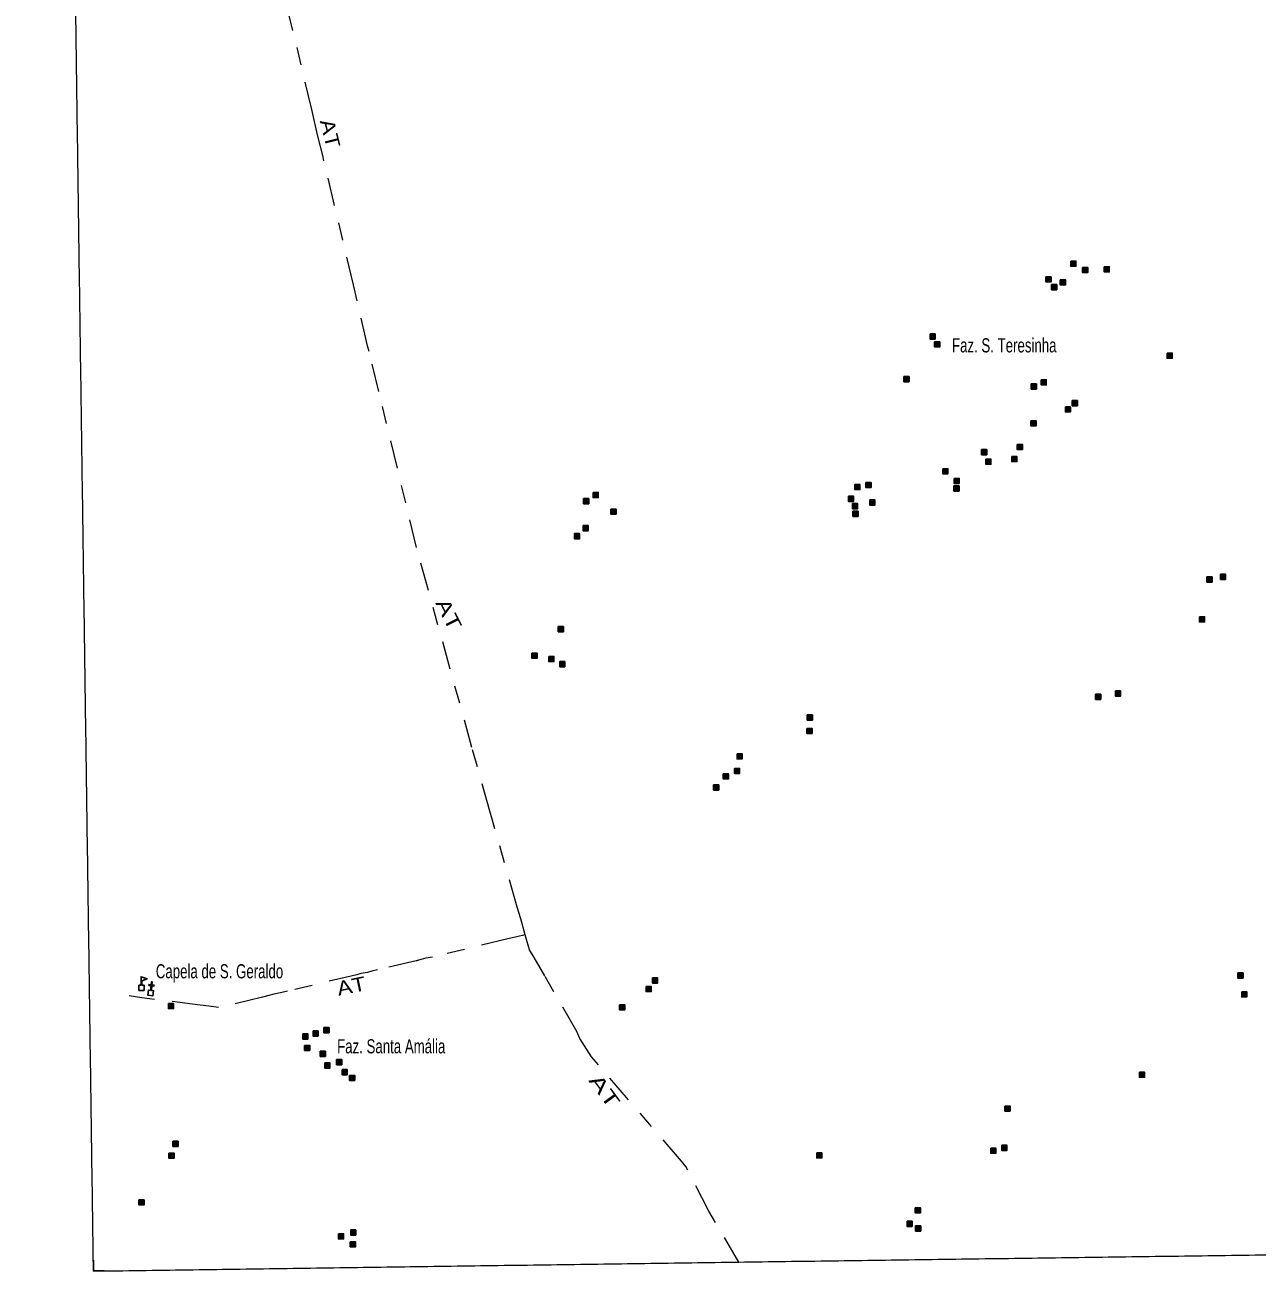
# Model space of a CAD drawing. Extents: x 265.7 to 292.1, y 7676.2 to 7704.2.
# Drawn here: x 265.72 to 272.68, y 7676.18 to 7683.22 of the extents above; entities that cross this region are included whole.
import ezdxf
from ezdxf.enums import TextEntityAlignment as Align

# ---------------------------------------------------------------- set-up
doc = ezdxf.new("R2010")
doc.units = 0
doc.header["$LTSCALE"] = 0.032
doc.linetypes.add('DOT_DASHED', pattern=[7.7, 5, -1.2, 0.3, -1.2])
for name, color, linetype, lineweight in [('2', 7, 'Continuous', 25), ('4', 7, 'Continuous', 25), ('56', 7, 'DOT_DASHED', 13), ('6', 7, 'Continuous', 25), ('63', 7, 'Continuous', 13)]:
    doc.layers.add(name, color=color, linetype=linetype, lineweight=lineweight)
doc.layers.add('61', color=7, linetype='Continuous')

msp = doc.modelspace()

# ---------------------------------------------------------------- hatches: boundary and pattern name
at = {"layer": '2'}
for points in [[(271.6304, 7681.8855), (271.6594, 7681.8855), (271.6594, 7681.8565), (271.6304, 7681.8565)], [(271.6974, 7681.8498), (271.7264, 7681.8498), (271.7264, 7681.8208), (271.6974, 7681.8208)], [(271.8193, 7681.8532), (271.8483, 7681.8532), (271.8483, 7681.8242), (271.8193, 7681.8242)], [(271.4902, 7681.7962), (271.5192, 7681.7962), (271.5192, 7681.7672), (271.4902, 7681.7672)], [(271.5223, 7681.7523), (271.5513, 7681.7523), (271.5513, 7681.7233), (271.5223, 7681.7233)], [(271.5707, 7681.7797), (271.5997, 7681.7797), (271.5997, 7681.7507), (271.5707, 7681.7507)], [(270.8346, 7681.4738), (270.8636, 7681.4738), (270.8636, 7681.4448), (270.8346, 7681.4448)], [(270.8605, 7681.4294), (270.8895, 7681.4294), (270.8895, 7681.4004), (270.8605, 7681.4004)], [(272.1751, 7681.3649), (272.2041, 7681.3649), (272.2041, 7681.3359), (272.1751, 7681.3359)], [(270.6869, 7681.2325), (270.7159, 7681.2325), (270.7159, 7681.2035), (270.6869, 7681.2035)], [(271.4069, 7681.1906), (271.4359, 7681.1906), (271.4359, 7681.1616), (271.4069, 7681.1616)], [(271.4631, 7681.2148), (271.4921, 7681.2148), (271.4921, 7681.1858), (271.4631, 7681.1858)], [(271.5997, 7681.0615), (271.6287, 7681.0615), (271.6287, 7681.0325), (271.5997, 7681.0325)], [(271.6385, 7681.097), (271.6675, 7681.097), (271.6675, 7681.068), (271.6385, 7681.068)], [(271.4052, 7680.9824), (271.4342, 7680.9824), (271.4342, 7680.9534), (271.4052, 7680.9534)], [(271.3277, 7680.8492), (271.3567, 7680.8492), (271.3567, 7680.8202), (271.3277, 7680.8202)], [(271.1259, 7680.8201), (271.1549, 7680.8201), (271.1549, 7680.7911), (271.1259, 7680.7911)], [(271.1502, 7680.766), (271.1792, 7680.766), (271.1792, 7680.737), (271.1502, 7680.737)], [(271.2971, 7680.7806), (271.3261, 7680.7806), (271.3261, 7680.7516), (271.2971, 7680.7516)], [(270.9065, 7680.712), (270.9355, 7680.712), (270.9355, 7680.683), (270.9065, 7680.683)], [(270.4093, 7680.6224), (270.4383, 7680.6224), (270.4383, 7680.5934), (270.4093, 7680.5934)], [(270.4722, 7680.6337), (270.5012, 7680.6337), (270.5012, 7680.6047), (270.4722, 7680.6047)], [(270.9695, 7680.6144), (270.9985, 7680.6144), (270.9985, 7680.5854), (270.9695, 7680.5854)], [(270.9711, 7680.6572), (271.0001, 7680.6572), (271.0001, 7680.6282), (270.9711, 7680.6282)], [(268.93, 7680.578), (268.959, 7680.578), (268.959, 7680.549), (268.93, 7680.549)], [(270.3731, 7680.5562), (270.4021, 7680.5562), (270.4021, 7680.5272), (270.3731, 7680.5272)], [(268.876, 7680.5426), (268.905, 7680.5426), (268.905, 7680.5136), (268.876, 7680.5136)], [(269.0309, 7680.4837), (269.0599, 7680.4837), (269.0599, 7680.4547), (269.0309, 7680.4547)], [(270.3964, 7680.5143), (270.4254, 7680.5143), (270.4254, 7680.4853), (270.3964, 7680.4853)], [(270.4941, 7680.5353), (270.5231, 7680.5353), (270.5231, 7680.5063), (270.4941, 7680.5063)], [(270.3989, 7680.4715), (270.4279, 7680.4715), (270.4279, 7680.4425), (270.3989, 7680.4425)], [(268.8244, 7680.3448), (268.8534, 7680.3448), (268.8534, 7680.3158), (268.8244, 7680.3158)], [(268.8734, 7680.39), (268.9024, 7680.39), (268.9024, 7680.361), (268.8734, 7680.361)], [(272.4003, 7680.1002), (272.4293, 7680.1002), (272.4293, 7680.0712), (272.4003, 7680.0712)], [(272.477, 7680.1148), (272.506, 7680.1148), (272.506, 7680.0858), (272.477, 7680.0858)], [(272.3575, 7679.8752), (272.3865, 7679.8752), (272.3865, 7679.8462), (272.3575, 7679.8462)], [(268.7331, 7679.8193), (268.7621, 7679.8193), (268.7621, 7679.7903), (268.7331, 7679.7903)], [(268.5839, 7679.6693), (268.6129, 7679.6693), (268.6129, 7679.6403), (268.5839, 7679.6403)], [(268.679, 7679.6507), (268.708, 7679.6507), (268.708, 7679.6217), (268.679, 7679.6217)], [(268.7411, 7679.6217), (268.7701, 7679.6217), (268.7701, 7679.5927), (268.7411, 7679.5927)], [(271.7709, 7679.4368), (271.7999, 7679.4368), (271.7999, 7679.4078), (271.7709, 7679.4078)], [(271.883, 7679.4554), (271.912, 7679.4554), (271.912, 7679.4264), (271.883, 7679.4264)], [(270.1407, 7679.3198), (270.1697, 7679.3198), (270.1697, 7679.2908), (270.1407, 7679.2908)], [(270.1386, 7679.2441), (270.1676, 7679.2441), (270.1676, 7679.2151), (270.1386, 7679.2151)], [(269.7435, 7679.1003), (269.7725, 7679.1003), (269.7725, 7679.0713), (269.7435, 7679.0713)], [(269.729, 7679.0181), (269.758, 7679.0181), (269.758, 7678.9891), (269.729, 7678.9891)], [(269.6111, 7678.9244), (269.6401, 7678.9244), (269.6401, 7678.8954), (269.6111, 7678.8954)], [(269.666, 7678.9873), (269.695, 7678.9873), (269.695, 7678.9583), (269.666, 7678.9583)], [(269.2658, 7677.8333), (269.2948, 7677.8333), (269.2948, 7677.8043), (269.2658, 7677.8043)], [(272.5755, 7677.8615), (272.6045, 7677.8615), (272.6045, 7677.8325), (272.5755, 7677.8325)], [(269.2295, 7677.7848), (269.2585, 7677.7848), (269.2585, 7677.7558), (269.2295, 7677.7558)], [(272.5965, 7677.7549), (272.6255, 7677.7549), (272.6255, 7677.7259), (272.5965, 7677.7259)], [(266.5291, 7677.6888), (266.5581, 7677.6888), (266.5581, 7677.6598), (266.5291, 7677.6598)], [(269.0801, 7677.6816), (269.1091, 7677.6816), (269.1091, 7677.6526), (269.0801, 7677.6526)], [(267.2885, 7677.517), (267.3175, 7677.517), (267.3175, 7677.488), (267.2885, 7677.488)], [(267.3465, 7677.5337), (267.3755, 7677.5337), (267.3755, 7677.5047), (267.3465, 7677.5047)], [(267.408, 7677.5523), (267.437, 7677.5523), (267.437, 7677.5233), (267.408, 7677.5233)], [(267.299, 7677.4523), (267.328, 7677.4523), (267.328, 7677.4233), (267.299, 7677.4233)], [(267.3878, 7677.4191), (267.4168, 7677.4191), (267.4168, 7677.3901), (267.3878, 7677.3901)], [(267.4127, 7677.353), (267.4417, 7677.353), (267.4417, 7677.324), (267.4127, 7677.324)], [(267.4797, 7677.3717), (267.5087, 7677.3717), (267.5087, 7677.3427), (267.4797, 7677.3427)], [(267.5113, 7677.3151), (267.5403, 7677.3151), (267.5403, 7677.2861), (267.5113, 7677.2861)], [(267.5532, 7677.2828), (267.5822, 7677.2828), (267.5822, 7677.2538), (267.5532, 7677.2538)], [(272.0186, 7677.3006), (272.0476, 7677.3006), (272.0476, 7677.2716), (272.0186, 7677.2716)], [(271.2584, 7677.1094), (271.2874, 7677.1094), (271.2874, 7677.0804), (271.2584, 7677.0804)], [(266.5549, 7676.9099), (266.5839, 7676.9099), (266.5839, 7676.8809), (266.5549, 7676.8809)], [(271.2402, 7676.8878), (271.2692, 7676.8878), (271.2692, 7676.8588), (271.2402, 7676.8588)], [(266.5322, 7676.843), (266.5612, 7676.843), (266.5612, 7676.814), (266.5322, 7676.814)], [(270.1947, 7676.8447), (270.2237, 7676.8447), (270.2237, 7676.8157), (270.1947, 7676.8157)], [(271.1778, 7676.8711), (271.2068, 7676.8711), (271.2068, 7676.8421), (271.1778, 7676.8421)], [(266.3628, 7676.5791), (266.3918, 7676.5791), (266.3918, 7676.5501), (266.3628, 7676.5501)], [(270.7516, 7676.5339), (270.7806, 7676.5339), (270.7806, 7676.5049), (270.7516, 7676.5049)], [(267.5596, 7676.4089), (267.5886, 7676.4089), (267.5886, 7676.3799), (267.5596, 7676.3799)], [(270.7047, 7676.4581), (270.7337, 7676.4581), (270.7337, 7676.4291), (270.7047, 7676.4291)], [(270.7532, 7676.4318), (270.7822, 7676.4318), (270.7822, 7676.4028), (270.7532, 7676.4028)], [(267.4903, 7676.387), (267.5193, 7676.387), (267.5193, 7676.358), (267.4903, 7676.358)], [(267.5572, 7676.3418), (267.5862, 7676.3418), (267.5862, 7676.3128), (267.5572, 7676.3128)]]:
    msp.add_hatch(color=256, dxfattribs=at).paths.add_polyline_path(points)

# ---------------------------------------------------------------- linework, layer by layer
for points in [[(271.6304, 7681.8855), (271.6594, 7681.8855), (271.6594, 7681.8565), (271.6304, 7681.8565)], [(271.6974, 7681.8498), (271.7264, 7681.8498), (271.7264, 7681.8208), (271.6974, 7681.8208)], [(271.8193, 7681.8532), (271.8483, 7681.8532), (271.8483, 7681.8242), (271.8193, 7681.8242)], [(271.4902, 7681.7962), (271.5192, 7681.7962), (271.5192, 7681.7672), (271.4902, 7681.7672)], [(271.5223, 7681.7523), (271.5513, 7681.7523), (271.5513, 7681.7233), (271.5223, 7681.7233)], [(271.5707, 7681.7797), (271.5997, 7681.7797), (271.5997, 7681.7507), (271.5707, 7681.7507)], [(270.8346, 7681.4738), (270.8636, 7681.4738), (270.8636, 7681.4448), (270.8346, 7681.4448)], [(270.8605, 7681.4294), (270.8895, 7681.4294), (270.8895, 7681.4004), (270.8605, 7681.4004)], [(272.1751, 7681.3649), (272.2041, 7681.3649), (272.2041, 7681.3359), (272.1751, 7681.3359)], [(270.6869, 7681.2325), (270.7159, 7681.2325), (270.7159, 7681.2035), (270.6869, 7681.2035)], [(271.4069, 7681.1906), (271.4359, 7681.1906), (271.4359, 7681.1616), (271.4069, 7681.1616)], [(271.4631, 7681.2148), (271.4921, 7681.2148), (271.4921, 7681.1858), (271.4631, 7681.1858)], [(271.5997, 7681.0615), (271.6287, 7681.0615), (271.6287, 7681.0325), (271.5997, 7681.0325)], [(271.6385, 7681.097), (271.6675, 7681.097), (271.6675, 7681.068), (271.6385, 7681.068)], [(271.4052, 7680.9824), (271.4342, 7680.9824), (271.4342, 7680.9534), (271.4052, 7680.9534)], [(271.3277, 7680.8492), (271.3567, 7680.8492), (271.3567, 7680.8202), (271.3277, 7680.8202)], [(271.1259, 7680.8201), (271.1549, 7680.8201), (271.1549, 7680.7911), (271.1259, 7680.7911)], [(271.1502, 7680.766), (271.1792, 7680.766), (271.1792, 7680.737), (271.1502, 7680.737)], [(271.2971, 7680.7806), (271.3261, 7680.7806), (271.3261, 7680.7516), (271.2971, 7680.7516)], [(270.9065, 7680.712), (270.9355, 7680.712), (270.9355, 7680.683), (270.9065, 7680.683)], [(270.4093, 7680.6224), (270.4383, 7680.6224), (270.4383, 7680.5934), (270.4093, 7680.5934)], [(270.4722, 7680.6337), (270.5012, 7680.6337), (270.5012, 7680.6047), (270.4722, 7680.6047)], [(270.9695, 7680.6144), (270.9985, 7680.6144), (270.9985, 7680.5854), (270.9695, 7680.5854)], [(270.9711, 7680.6572), (271.0001, 7680.6572), (271.0001, 7680.6282), (270.9711, 7680.6282)], [(268.93, 7680.578), (268.959, 7680.578), (268.959, 7680.549), (268.93, 7680.549)], [(270.3731, 7680.5562), (270.4021, 7680.5562), (270.4021, 7680.5272), (270.3731, 7680.5272)], [(268.876, 7680.5426), (268.905, 7680.5426), (268.905, 7680.5136), (268.876, 7680.5136)], [(269.0309, 7680.4837), (269.0599, 7680.4837), (269.0599, 7680.4547), (269.0309, 7680.4547)], [(270.3964, 7680.5143), (270.4254, 7680.5143), (270.4254, 7680.4853), (270.3964, 7680.4853)], [(270.4941, 7680.5353), (270.5231, 7680.5353), (270.5231, 7680.5063), (270.4941, 7680.5063)], [(270.3989, 7680.4715), (270.4279, 7680.4715), (270.4279, 7680.4425), (270.3989, 7680.4425)], [(268.8244, 7680.3448), (268.8534, 7680.3448), (268.8534, 7680.3158), (268.8244, 7680.3158)], [(268.8734, 7680.39), (268.9024, 7680.39), (268.9024, 7680.361), (268.8734, 7680.361)], [(272.4003, 7680.1002), (272.4293, 7680.1002), (272.4293, 7680.0712), (272.4003, 7680.0712)], [(272.477, 7680.1148), (272.506, 7680.1148), (272.506, 7680.0858), (272.477, 7680.0858)], [(272.3575, 7679.8752), (272.3865, 7679.8752), (272.3865, 7679.8462), (272.3575, 7679.8462)], [(268.7331, 7679.8193), (268.7621, 7679.8193), (268.7621, 7679.7903), (268.7331, 7679.7903)], [(268.5839, 7679.6693), (268.6129, 7679.6693), (268.6129, 7679.6403), (268.5839, 7679.6403)], [(268.679, 7679.6507), (268.708, 7679.6507), (268.708, 7679.6217), (268.679, 7679.6217)], [(268.7411, 7679.6217), (268.7701, 7679.6217), (268.7701, 7679.5927), (268.7411, 7679.5927)], [(271.7709, 7679.4368), (271.7999, 7679.4368), (271.7999, 7679.4078), (271.7709, 7679.4078)], [(271.883, 7679.4554), (271.912, 7679.4554), (271.912, 7679.4264), (271.883, 7679.4264)], [(270.1407, 7679.3198), (270.1697, 7679.3198), (270.1697, 7679.2908), (270.1407, 7679.2908)], [(270.1386, 7679.2441), (270.1676, 7679.2441), (270.1676, 7679.2151), (270.1386, 7679.2151)], [(269.7435, 7679.1003), (269.7725, 7679.1003), (269.7725, 7679.0713), (269.7435, 7679.0713)], [(269.729, 7679.0181), (269.758, 7679.0181), (269.758, 7678.9891), (269.729, 7678.9891)], [(269.6111, 7678.9244), (269.6401, 7678.9244), (269.6401, 7678.8954), (269.6111, 7678.8954)], [(269.666, 7678.9873), (269.695, 7678.9873), (269.695, 7678.9583), (269.666, 7678.9583)], [(269.2658, 7677.8333), (269.2948, 7677.8333), (269.2948, 7677.8043), (269.2658, 7677.8043)], [(272.5755, 7677.8615), (272.6045, 7677.8615), (272.6045, 7677.8325), (272.5755, 7677.8325)], [(269.2295, 7677.7848), (269.2585, 7677.7848), (269.2585, 7677.7558), (269.2295, 7677.7558)], [(272.5965, 7677.7549), (272.6255, 7677.7549), (272.6255, 7677.7259), (272.5965, 7677.7259)], [(266.5291, 7677.6888), (266.5581, 7677.6888), (266.5581, 7677.6598), (266.5291, 7677.6598)], [(269.0801, 7677.6816), (269.1091, 7677.6816), (269.1091, 7677.6526), (269.0801, 7677.6526)], [(267.2885, 7677.517), (267.3175, 7677.517), (267.3175, 7677.488), (267.2885, 7677.488)], [(267.3465, 7677.5337), (267.3755, 7677.5337), (267.3755, 7677.5047), (267.3465, 7677.5047)], [(267.408, 7677.5523), (267.437, 7677.5523), (267.437, 7677.5233), (267.408, 7677.5233)], [(267.299, 7677.4523), (267.328, 7677.4523), (267.328, 7677.4233), (267.299, 7677.4233)], [(267.3878, 7677.4191), (267.4168, 7677.4191), (267.4168, 7677.3901), (267.3878, 7677.3901)], [(267.4127, 7677.353), (267.4417, 7677.353), (267.4417, 7677.324), (267.4127, 7677.324)], [(267.4797, 7677.3717), (267.5087, 7677.3717), (267.5087, 7677.3427), (267.4797, 7677.3427)], [(267.5113, 7677.3151), (267.5403, 7677.3151), (267.5403, 7677.2861), (267.5113, 7677.2861)], [(267.5532, 7677.2828), (267.5822, 7677.2828), (267.5822, 7677.2538), (267.5532, 7677.2538)], [(272.0186, 7677.3006), (272.0476, 7677.3006), (272.0476, 7677.2716), (272.0186, 7677.2716)], [(271.2584, 7677.1094), (271.2874, 7677.1094), (271.2874, 7677.0804), (271.2584, 7677.0804)], [(266.5549, 7676.9099), (266.5839, 7676.9099), (266.5839, 7676.8809), (266.5549, 7676.8809)], [(271.2402, 7676.8878), (271.2692, 7676.8878), (271.2692, 7676.8588), (271.2402, 7676.8588)], [(266.5322, 7676.843), (266.5612, 7676.843), (266.5612, 7676.814), (266.5322, 7676.814)], [(270.1947, 7676.8447), (270.2237, 7676.8447), (270.2237, 7676.8157), (270.1947, 7676.8157)], [(271.1778, 7676.8711), (271.2068, 7676.8711), (271.2068, 7676.8421), (271.1778, 7676.8421)], [(266.3628, 7676.5791), (266.3918, 7676.5791), (266.3918, 7676.5501), (266.3628, 7676.5501)], [(270.7516, 7676.5339), (270.7806, 7676.5339), (270.7806, 7676.5049), (270.7516, 7676.5049)], [(267.5596, 7676.4089), (267.5886, 7676.4089), (267.5886, 7676.3799), (267.5596, 7676.3799)], [(270.7047, 7676.4581), (270.7337, 7676.4581), (270.7337, 7676.4291), (270.7047, 7676.4291)], [(270.7532, 7676.4318), (270.7822, 7676.4318), (270.7822, 7676.4028), (270.7532, 7676.4028)], [(267.4903, 7676.387), (267.5193, 7676.387), (267.5193, 7676.358), (267.4903, 7676.358)], [(267.5572, 7676.3418), (267.5862, 7676.3418), (267.5862, 7676.3128), (267.5572, 7676.3128)]]:
    msp.add_lwpolyline(points, close=True, dxfattribs=at)
at = {"layer": '4'}
for points in [[(266.3745, 7677.7918), (266.3745, 7677.8402), (266.4084, 7677.8286), (266.3794, 7677.8179), (266.3794, 7677.7918)], [(266.3794, 7677.7918), (266.3915, 7677.7918), (266.3915, 7677.7628), (266.3625, 7677.7628), (266.3625, 7677.7918), (266.3745, 7677.7918)]]:
    msp.add_lwpolyline(points, dxfattribs=at)
at = {"layer": '56'}
for points in [[(269.7537, 7676.2274), (269.585, 7676.5156), (269.455, 7676.7673), (269.4306, 7676.797), (268.921, 7677.3872), (268.8559, 7677.4919), (268.838, 7677.5303), (268.6569, 7677.8446), (268.5972, 7677.9487), (268.5707, 7677.9925), (268.5542, 7678.0507), (268.5466, 7678.0769), (268.5222, 7678.1676), (268.5015, 7678.2343), (268.3595, 7678.7303), (268.346, 7678.7768), (268.2451, 7679.1362), (267.9319, 7680.267), (267.7191, 7681.1473), (267.6632, 7681.3749), (267.6544, 7681.4066), (267.5753, 7681.7512), (267.4013, 7682.4814), (267.3726, 7682.5999), (267.3403, 7682.7419), (267.2124, 7683.2739)], [(268.5466, 7678.0769), (268.4992, 7678.0663), (268.4549, 7678.056), (268.0212, 7677.9503), (267.9842, 7677.945), (267.9436, 7677.9341), (267.9391, 7677.932), (267.9359, 7677.932), (267.9327, 7677.9303), (267.9302, 7677.9295), (267.7118, 7677.879), (267.6786, 7677.8723), (267.6537, 7677.8649), (267.6176, 7677.8586), (267.5941, 7677.8512), (267.2032, 7677.7585), (267.163, 7677.7487), (267.1256, 7677.7414), (267.0966, 7677.7341), (267.0619, 7677.725), (266.8131, 7677.6656), (266.7585, 7677.6733), (266.7086, 7677.6791), (266.4512, 7677.7119), (266.3796, 7677.7202), (266.3068, 7677.7319)]]:
    msp.add_lwpolyline(points, dxfattribs=at)
at = {"layer": '6'}
for points in [[(266.428, 7677.7631), (266.4307, 7677.7901), (266.4187, 7677.7913), (266.4191, 7677.7962), (266.4312, 7677.795), (266.4328, 7677.8113), (266.4376, 7677.8108), (266.436, 7677.7945), (266.448, 7677.7933), (266.4475, 7677.7884), (266.4355, 7677.7896), (266.4328, 7677.7626)], [(266.4328, 7677.7626), (266.4448, 7677.7614), (266.4419, 7677.7326), (266.4131, 7677.7355), (266.416, 7677.7643), (266.428, 7677.7631)]]:
    msp.add_lwpolyline(points, dxfattribs=at)
at = {"layer": '63', "lineweight": 25}
msp.add_lwpolyline([(266.1061, 7676.239), (266.1061, 7676.1774), (266.1668, 7676.1774)], dxfattribs=at)
at = {"layer": '63'}
for points in [[(266.1055, 7676.1764), (266.0976, 7676.7414), (266.0896, 7677.3064), (266.0817, 7677.8713), (266.0737, 7678.4363), (266.0658, 7679.0013), (266.0578, 7679.5663), (266.0499, 7680.1313), (266.0419, 7680.6963), (266.034, 7681.2613), (266.026, 7681.8263), (266.0181, 7682.3913), (266.0102, 7682.9563), (266.0022, 7683.5212), (265.9943, 7684.0862), (265.9864, 7684.6512), (265.9785, 7685.2162), (265.9705, 7685.7812), (265.9626, 7686.3462), (265.9547, 7686.9112), (265.9468, 7687.4762), (265.9389, 7688.0411), (265.9309, 7688.6061), (265.923, 7689.1711), (265.9151, 7689.7361), (265.9072, 7690.3011), (265.8993, 7690.8661), (265.8914, 7691.4311), (265.8835, 7691.996), (265.8756, 7692.561), (265.8677, 7693.126), (265.8598, 7693.691), (265.8519, 7694.256), (265.844, 7694.821), (265.8361, 7695.3859), (265.8282, 7695.9509), (265.8203, 7696.5159), (265.8124, 7697.0809), (265.8045, 7697.6459), (265.7967, 7698.2108), (265.7888, 7698.7758), (265.7809, 7699.3408), (265.773, 7699.9058), (265.7651, 7700.4708), (265.7573, 7701.0357), (265.7494, 7701.6007), (265.7415, 7702.1657), (265.7337, 7702.7307), (265.7258, 7703.2957), (265.7179, 7703.8606)], [(266.1055, 7676.1764), (266.6361, 7676.1838), (267.1667, 7676.1913), (267.6972, 7676.1987), (268.2278, 7676.2061), (268.7584, 7676.2135), (269.2889, 7676.2209), (269.8195, 7676.2283), (270.3501, 7676.2356), (270.8806, 7676.2429), (271.4112, 7676.2502), (271.9418, 7676.2575), (272.4723, 7676.2648), (273.0029, 7676.2721), (273.5335, 7676.2793), (274.064, 7676.2865), (274.5946, 7676.2937), (275.1251, 7676.3009), (275.6557, 7676.3081), (276.1862, 7676.3153), (276.7168, 7676.3224), (277.2473, 7676.3295), (277.7779, 7676.3366), (278.3084, 7676.3437), (278.839, 7676.3508), (279.3695, 7676.3578), (279.9, 7676.3649), (280.4306, 7676.3719), (280.9611, 7676.3789), (281.4917, 7676.3859), (282.0222, 7676.3929), (282.5527, 7676.3998), (283.0833, 7676.4067), (283.6138, 7676.4137), (284.1443, 7676.4206), (284.6749, 7676.4275), (285.2054, 7676.4343), (285.7359, 7676.4412), (286.2665, 7676.448), (286.797, 7676.4548), (287.3275, 7676.4616), (287.858, 7676.4684), (288.3886, 7676.4752), (288.9191, 7676.4819), (289.4496, 7676.4887), (289.9801, 7676.4954), (290.5106, 7676.5021), (291.0411, 7676.5087), (291.5717, 7676.5154), (292.1022, 7676.5221)]]:
    msp.add_spline(points, degree=3, dxfattribs=at)

# ---------------------------------------------------------------- texts
at = {"layer": '61'}
for rotation, width, p in [(283.988, 1.2, (267.4047, 7682.5973)), (296.688, 1.35, (268.0779, 7679.871)), (11.654, 1.2, (267.5713, 7677.7488)), (306.235, 1.5, (268.9622, 7677.1704))]:
    msp.add_text('AT', height=0.08, rotation=rotation, dxfattribs=dict(at, width=width)).set_placement(p, align=Align.CENTER)
at = {"layer": '61', "width": 0.7}
for s, p in [('Faz. S. Teresinha', (270.9588, 7681.3692)), ('Capela de S. Geraldo', (266.4578, 7677.8311)), ('Faz. Santa Amália', (267.4828, 7677.4071))]:
    msp.add_text(s, height=0.08, dxfattribs=at).set_placement(p)

doc.saveas('drawing.dxf')
